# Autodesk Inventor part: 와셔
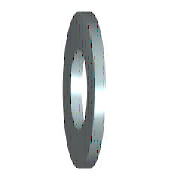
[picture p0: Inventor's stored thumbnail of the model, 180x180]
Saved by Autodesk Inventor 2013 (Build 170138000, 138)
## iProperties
IsCustomPart: 0
Created: 2012-02
Part Number: 와셔
Material: 강철, 연강
Description: 평면 와셔 - 일반 시리즈 - 제품 등급 C
Document SubType Name: Modeling
Standard: ISO 7091
Designer: mduedu
Standard Revision: Second edition 2000-06-01
Standards Organization: ISO
Language: ko-KR
Size Designation: ST 4 - 100 HV
Categories: <MemberInstance><Categories><Category DisplayName="조임쇠" InternalName="e4da775c-781d-43d5-af7c-5136215cf5a6" Mnemonic="FSTN"><Category DisplayName="와셔" InternalN
Density: 7.86 g/cm^3
Mass: 0.492315 g
Surface Area: 1.70824 cm^2
Volume: 0.0626355 cm^3
Author: mduedu
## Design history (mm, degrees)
sketch "스케치"
  geometry: C1 r 5 at (0, 0); C2 r 2.25 at (0, 0); 1 further point
  constraints: 2 centre point, 2 coincident
  dimensions: "d0" = 4.5 diameter of C2 (= SD1); "d1" = 10 diameter of C1 (= SD2)
extrude "본체" new body sketch "스케치" distance "d2" = 1 (= SD); taper "d3" = 0 deg
workaxis "Work Axis1"
workplane "Work Plane1"
body "Solid1"
other parameters: "SD1" = 4.5 [user parameter; used in 1 equation term], "SD2" = 10 [user parameter; used in 1 equation term], "SD" = 1 [user parameter; used in 1 equation term], "d4" = 0, "d5" = 0, "d6" = 0, "d7" = 0, "NND" = 4 [user parameter]
